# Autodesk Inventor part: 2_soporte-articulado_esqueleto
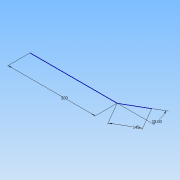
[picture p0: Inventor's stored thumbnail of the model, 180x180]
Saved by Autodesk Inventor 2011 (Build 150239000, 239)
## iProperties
Created: 2020-12
Part Number: 2_soporte-articulado_esqueleto
Document SubType Name: Modeling
Designer: PC
Density: 1 g/cm^3
Author: PC
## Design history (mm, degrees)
sketch "Sketch1"
  geometry: L1 (0, 0)-(500, 0); L2 (500, 0)-(625.574, 72.5)
  constraints: 4 end point, 1 horizontal
  dimensions: "d0" = 500 dimension on L1.start L1.end L1 L2.end L2; "d0" = 500 distance of L1.start L1.end; "d1" = 30 deg angle of L1 L2; "d2" = 145 distance of L1.end L2.end
